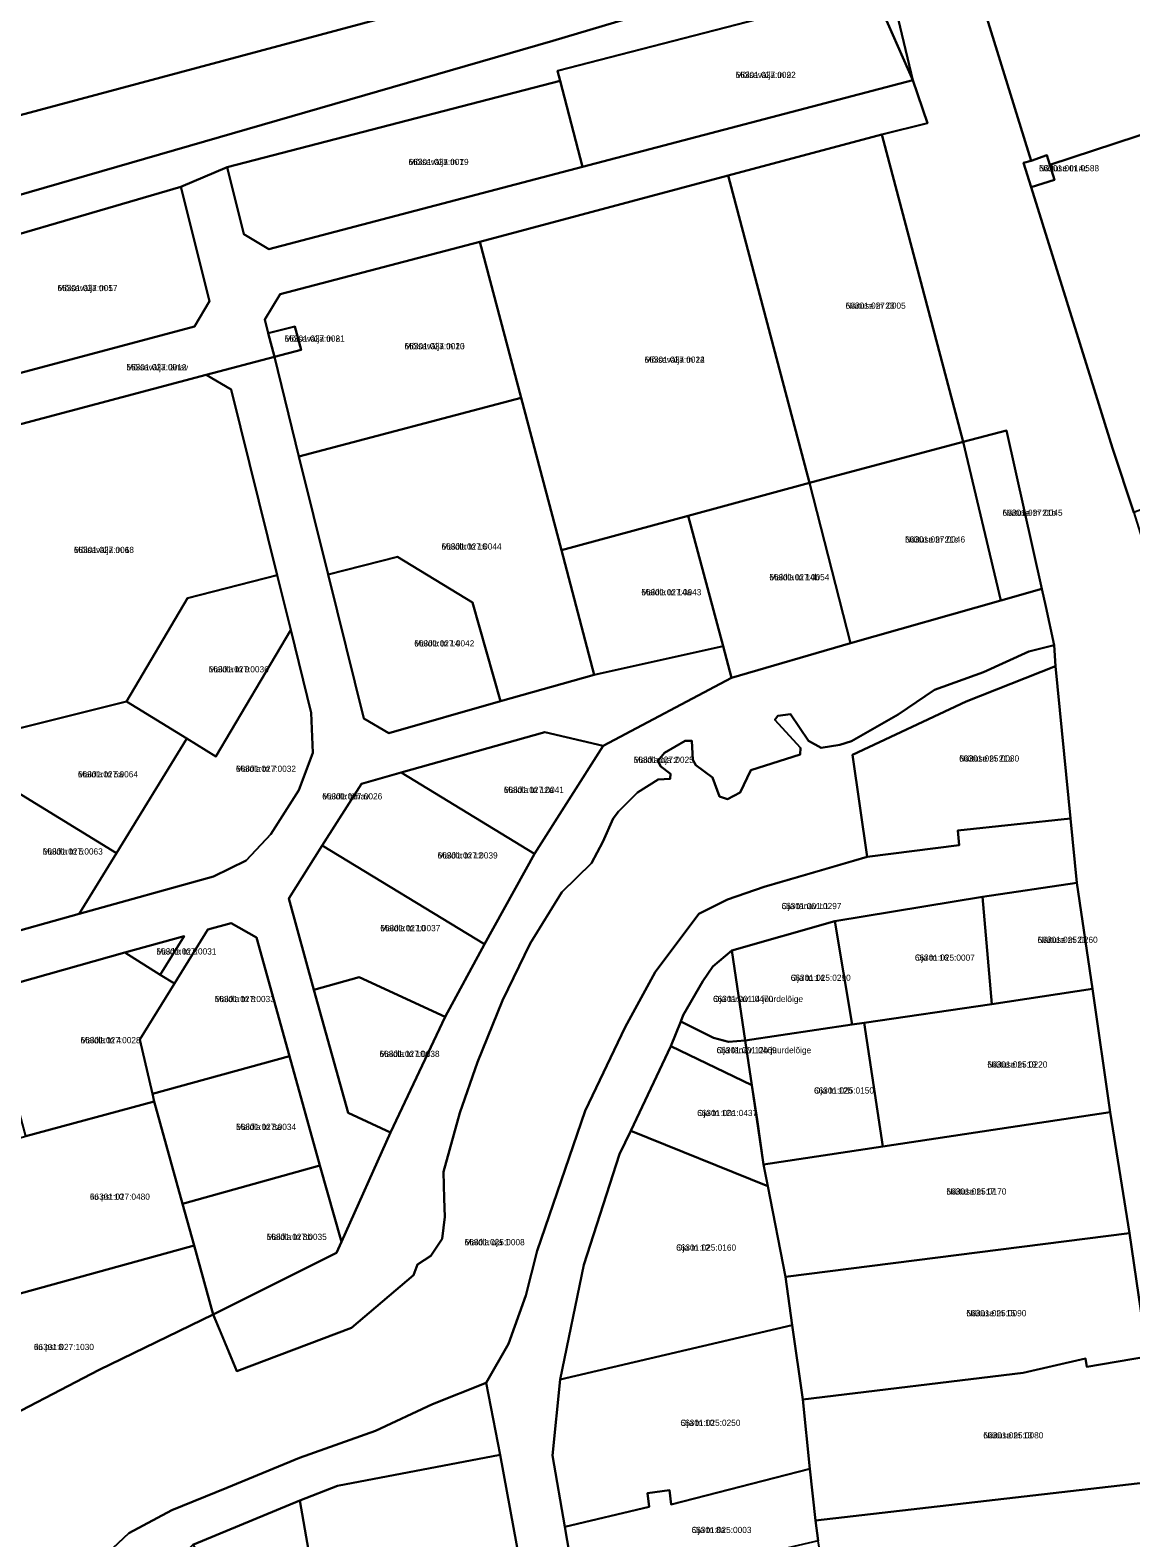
# Model space of a CAD drawing. Extents: x 632278 to 636344, y 6578401 to 6583362.
# Drawn here: x 633256.9 to 633522.9, y 6581626.2 to 6581990.5 of the extents above; entities that cross this region are included whole.
import ezdxf

# ---------------------------------------------------------------- set-up
doc = ezdxf.new("R2010")
doc.units = 0
for name, color, linetype in [('L_AADRESS', 7, 'Continuous'), ('PIIR', 7, 'Continuous'), ('TUNNUS', 7, 'Continuous')]:
    doc.layers.add(name, color=color, linetype=linetype)

msp = doc.modelspace()

# ---------------------------------------------------------------- linework, layer by layer
at = {"layer": 'PIIR'}
for points in [[(633468.65, 6582027.37), (633117.3, 6581933.19), (633092.94, 6581927.34), (633069.22, 6581920.67), (633045.02, 6581914.19), (633045.28, 6581913.19), (633021.21, 6581906.88), (632996.93, 6581900.69), (632973.03, 6581894.3), (632949.09, 6581888.13), (632929.99, 6581882.98), (632922.41, 6581910.15), (633111.38, 6581959.61), (633249.26, 6581995.68), (633462.58, 6582051.42), (633730.08, 6582121.51), (633857.97, 6582155.11), (633862.14, 6582132.61)], [(633580.94, 6582031.55), (633592.88, 6581987.35), (633503.33, 6581957.89), (633502.57, 6581960.28), (633498.8, 6581958.88), (633484.12, 6582006.27)], [(633462.31, 6582011.45), (633470.22, 6581978.42), (633460.53, 6582000.37), (633384.34, 6581980.64), (633384.99, 6581978.2), (633304.52, 6581957.35), (633293.32, 6581952.62), (633225.99, 6581932.99), (633176.07, 6581918.5), (633151, 6581905.14), (633144.21, 6581893.52), (633147.4, 6581879.57), (633151.84, 6581860.05), (633155.06, 6581838.11), (633140.94, 6581889.14), (633140.47, 6581896.81), (633142.13, 6581902.16), (633145.51, 6581907.72), (633153.21, 6581914.67), (633162.26, 6581920.12), (633173.34, 6581925.07), (633203.93, 6581936.06), (633383.2, 6581987.92)], [(633460.53, 6582000.37), (633470.22, 6581978.42), (633390.37, 6581957.42), (633384.99, 6581978.2), (633384.34, 6581980.64)], [(633592.88, 6581987.35), (633613.38, 6581912.42), (633613.99, 6581908.56), (633556.31, 6581886.43), (633523.61, 6581873.92), (633518.47, 6581889.48), (633513.31, 6581906.06), (633498.83, 6581952.55), (633504.43, 6581954.3), (633503.33, 6581957.89)], [(633384.99, 6581978.2), (633390.37, 6581957.42), (633314.61, 6581937.53), (633308.59, 6581941.15), (633304.52, 6581957.35)], [(633425.55, 6581955.33), (633462.71, 6581965.22), (633482.39, 6581890.96), (633445.22, 6581881.09)], [(633498.83, 6581952.55), (633496.97, 6581958.43), (633498.8, 6581958.88), (633502.57, 6581960.28), (633503.33, 6581957.89), (633504.43, 6581954.3)], [(633293.32, 6581952.62), (633300.24, 6581925), (633296.61, 6581918.84), (633234.08, 6581902.2), (633225.99, 6581932.99)], [(633425.55, 6581955.33), (633445.22, 6581881.09), (633415.95, 6581873.12), (633385.29, 6581864.78), (633375.6, 6581901.6), (633365.6, 6581939.32)], [(633365.6, 6581939.32), (633375.6, 6581901.6), (633321.87, 6581887.42), (633315.94, 6581911.51), (633322.39, 6581913.19), (633320.91, 6581918.86), (633314.47, 6581917.28), (633313.68, 6581920.54), (633317.31, 6581926.65)], [(633320.91, 6581918.86), (633322.39, 6581913.19), (633315.94, 6581911.51), (633314.47, 6581917.28)], [(633299.46, 6581907.2), (633305.51, 6581903.66), (633316.61, 6581858.79), (633294.92, 6581853.21), (633280.25, 6581828.25), (633251.58, 6581821.06), (633244.66, 6581846.44), (633225.92, 6581841.42), (633215.22, 6581880.7), (633226.99, 6581887.92)], [(633375.6, 6581901.6), (633385.29, 6581864.78), (633393.19, 6581834.69), (633370.57, 6581828.32), (633363.78, 6581852.14), (633345.66, 6581863.23), (633328.94, 6581858.91), (633321.87, 6581887.42)], [(633492.85, 6581893.71), (633501.36, 6581855.45), (633491.47, 6581852.68), (633482.39, 6581890.96)], [(633482.39, 6581890.96), (633491.47, 6581852.68), (633455.13, 6581842.33), (633445.22, 6581881.09)], [(633445.22, 6581881.09), (633455.13, 6581842.33), (633426.41, 6581833.95), (633424.36, 6581841.62), (633415.95, 6581873.12)], [(633415.95, 6581873.12), (633424.36, 6581841.62), (633393.19, 6581834.69), (633385.29, 6581864.78)], [(633345.66, 6581863.23), (633363.78, 6581852.14), (633370.57, 6581828.32), (633343.56, 6581820.62), (633337.56, 6581824.11), (633328.94, 6581858.91)], [(633316.61, 6581858.79), (633319.93, 6581845.53), (633301.84, 6581814.96), (633294.78, 6581819.28), (633280.25, 6581828.25), (633294.92, 6581853.21)], [(633501.36, 6581855.45), (633502.31, 6581851.17), (633504.37, 6581841.88), (633498.21, 6581840.3), (633487.25, 6581835.35), (633475.45, 6581831.05), (633466.69, 6581825.13), (633455.38, 6581818.69), (633452.59, 6581817.76), (633448.05, 6581817.02), (633445.01, 6581818.76), (633440.68, 6581825.17), (633437.59, 6581824.77), (633436.83, 6581823.79), (633443.06, 6581817.06), (633443, 6581815.44), (633431.04, 6581811.67), (633428.45, 6581806.29), (633425.43, 6581804.67), (633423.51, 6581805.27), (633421.82, 6581809.9), (633417.79, 6581812.83), (633417.05, 6581814.15), (633416.84, 6581818.71), (633415.23, 6581818.78), (633410.23, 6581815.86), (633408.57, 6581813.9), (633409.31, 6581812.58), (633411.67, 6581810.8), (633411.6, 6581809.58), (633408.64, 6581809.44), (633403.66, 6581806.26), (633399.1, 6581801.65), (633397.81, 6581800.02), (633395.34, 6581794.38), (633392.58, 6581789.2), (633385.38, 6581782.22), (633377.76, 6581769.77), (633371.05, 6581756.04), (633365.01, 6581741.12), (633360.77, 6581728.89), (633356.83, 6581714.61), (633356.94, 6581708.2), (633357.17, 6581703.71), (633356.52, 6581698.4), (633353.77, 6581694.28), (633350.54, 6581692.26), (633349.54, 6581689.68), (633334.57, 6581676.88), (633306.84, 6581666.46), (633303, 6581675.83), (633301.19, 6581680.12), (633330.95, 6581695.04), (633332.17, 6581697.67), (633344.04, 6581724.09), (633357.22, 6581752.06), (633366.71, 6581769.58), (633378.77, 6581791.46), (633395.35, 6581817.58), (633426.41, 6581833.95), (633455.13, 6581842.33), (633491.47, 6581852.68)], [(633319.93, 6581845.53), (633324.83, 6581825.48), (633325.22, 6581815.86), (633321.84, 6581806.82), (633315.06, 6581796.22), (633309.13, 6581789.86), (633301.24, 6581785.98), (633268.76, 6581776.98), (633277.77, 6581791.59), (633294.78, 6581819.28), (633301.84, 6581814.96)], [(633455.63, 6581815.4), (633483.06, 6581828.25), (633504.64, 6581836.77), (633508.31, 6581800.02), (633481.05, 6581797.07), (633481.41, 6581793.53), (633459.16, 6581790.72)], [(633251.58, 6581821.06), (633280.25, 6581828.25), (633294.78, 6581819.28), (633277.77, 6581791.59), (633245.6, 6581811.37)], [(633381.26, 6581820.86), (633395.35, 6581817.58), (633378.77, 6581791.46), (633346.62, 6581811.07)], [(633239.57, 6581801.51), (633245.6, 6581811.37), (633277.77, 6581791.59), (633268.76, 6581776.98), (633248, 6581771.16)], [(633346.62, 6581811.07), (633378.77, 6581791.46), (633366.71, 6581769.58), (633327.51, 6581793.45), (633336.99, 6581808.35)], [(633327.51, 6581793.45), (633366.71, 6581769.58), (633357.22, 6581752.06), (633336.45, 6581761.65), (633325.5, 6581758.6), (633319.4, 6581780.68)], [(633487.07, 6581781.04), (633509.79, 6581784.45), (633513.64, 6581758.84), (633489.29, 6581755.15)], [(633487.06, 6581781.03), (633489.29, 6581755.14), (633458.46, 6581750.62), (633455.57, 6581750.22), (633451.36, 6581775.19)], [(633311.64, 6581771.23), (633319.64, 6581742.57), (633286.47, 6581733.48), (633283.46, 6581746.61), (633291.81, 6581760.11), (633299.88, 6581773.15), (633305.49, 6581774.73)], [(633426.51, 6581768.05), (633451.36, 6581775.19), (633455.57, 6581750.22), (633429.72, 6581746.33)], [(633294.17, 6581771.56), (633288.39, 6581762.23), (633279.79, 6581767.57)], [(633291.81, 6581760.11), (633283.46, 6581746.61), (633286.47, 6581733.48), (633286.91, 6581731.59), (633255.93, 6581723.22), (633246.43, 6581758.18), (633279.79, 6581767.57), (633288.39, 6581762.23)], [(633425.66, 6581746.06), (633422.02, 6581746.96), (633414.15, 6581750.94), (633414.75, 6581752.45), (633419.44, 6581760.66), (633421.86, 6581764.21), (633426.51, 6581768.05), (633429.72, 6581746.33)], [(633336.45, 6581761.65), (633357.22, 6581752.06), (633344.04, 6581724.09), (633333.78, 6581728.88), (633325.5, 6581758.6)], [(633458.46, 6581750.62), (633489.29, 6581755.15), (633513.64, 6581758.84), (633517.88, 6581729.04), (633462.92, 6581720.76)], [(633411.77, 6581745.01), (633414.15, 6581750.94), (633422.02, 6581746.96), (633425.66, 6581746.06), (633429.72, 6581746.33), (633431.31, 6581735.58)], [(633429.72, 6581746.33), (633455.57, 6581750.22), (633458.46, 6581750.62), (633462.92, 6581720.76), (633434.16, 6581716.36), (633431.31, 6581735.58)], [(633411.77, 6581745.01), (633431.31, 6581735.58), (633432.56, 6581727.24), (633434.16, 6581716.36), (633435.16, 6581711.15), (633402.06, 6581724.54)], [(633319.64, 6581742.57), (633326.94, 6581716.18), (633293.77, 6581706.88), (633286.91, 6581731.59), (633286.47, 6581733.48)], [(633244.94, 6581706.54), (633252.07, 6581708.73), (633248.95, 6581720.27), (633248.73, 6581721.25), (633255.93, 6581723.22), (633286.91, 6581731.59), (633293.77, 6581706.88), (633296.54, 6581696.84), (633250.78, 6581684.13)], [(633435.16, 6581711.15), (633434.16, 6581716.36), (633462.92, 6581720.76), (633517.88, 6581729.04), (633522.55, 6581699.81), (633439.42, 6581689.21)], [(633390.69, 6581692.12), (633399.32, 6581718.86), (633402.06, 6581724.54), (633435.16, 6581711.15), (633439.42, 6581689.21), (633441.05, 6581677.6), (633384.98, 6581664.44)], [(633326.94, 6581716.18), (633332.17, 6581697.67), (633330.95, 6581695.04), (633301.19, 6581680.12), (633296.54, 6581696.84), (633293.77, 6581706.88)], [(633441.05, 6581677.6), (633439.42, 6581689.21), (633522.55, 6581699.81), (633526.94, 6581670.03), (633512.23, 6581667.49), (633511.9, 6581669.49), (633496.87, 6581666.04), (633443.6, 6581659.61)], [(633230.25, 6581646.23), (633229.72, 6581649.31), (633235.54, 6581659.25), (633232.1, 6581672.26), (633230.76, 6581678.53), (633241.04, 6581681.44), (633250.78, 6581684.13), (633296.54, 6581696.84), (633301.19, 6581680.12), (633273.6, 6581666.8), (633245.43, 6581652.13)], [(633411.44, 6581637.68), (633406.08, 6581637), (633406.53, 6581633.67), (633386.1, 6581628.85), (633383.12, 6581646.09), (633384.98, 6581664.44), (633441.05, 6581677.6), (633443.6, 6581659.61), (633445.34, 6581642.81), (633411.82, 6581634.25)], [(633445.34, 6581642.81), (633443.6, 6581659.61), (633496.87, 6581666.04), (633511.9, 6581669.49), (633512.23, 6581667.49), (633526.94, 6581670.03), (633531.38, 6581640.09), (633446.66, 6581630.36)], [(633236.04, 6581567.1), (633245.27, 6581584.02), (633257.39, 6581602.5), (633270.57, 6581617.68), (633280.81, 6581627.28), (633291.21, 6581632.88), (633304.49, 6581638.25), (633322.01, 6581645.47), (633340.35, 6581652.06), (633354.15, 6581658.45), (633367.14, 6581663.61), (633370.5, 6581646.27), (633331.22, 6581638.78), (633322.09, 6581635.2), (633296.22, 6581624.47), (633281.68, 6581610.06), (633267.35, 6581595.76), (633246.75, 6581561.72)], [(633328.38, 6581599.16), (633322.09, 6581635.2), (633331.22, 6581638.78), (633370.5, 6581646.27), (633377.65, 6581607.17)], [(633386.1, 6581628.85), (633406.53, 6581633.67), (633406.08, 6581637), (633411.44, 6581637.68), (633411.82, 6581634.25), (633445.34, 6581642.81), (633446.66, 6581630.36), (633447.34, 6581625.47), (633388.99, 6581611.85)], [(633450.03, 6581608.95), (633447.34, 6581625.47), (633446.66, 6581630.36), (633531.38, 6581640.09), (633535.56, 6581610.73), (633451.66, 6581597.92)], [(633318.16, 6581595.97), (633318, 6581596.08), (633296.22, 6581624.47), (633322.09, 6581635.2), (633328.38, 6581599.16), (633328.54, 6581598.52)]]:
    msp.add_lwpolyline(points, close=True, dxfattribs=at)
for points in [[(633734.4, 6582070.6), (633580.94, 6582031.55), (633484.12, 6582006.27), (633462.31, 6582011.45), (633383.2, 6581987.92), (633203.93, 6581936.06), (633173.34, 6581925.07), (633162.26, 6581920.12), (633153.21, 6581914.67), (633145.51, 6581907.72), (633142.13, 6581902.16), (633123.55, 6581908.66), (633117.3, 6581933.19), (633468.65, 6582027.37), (633862.14, 6582132.61)], [(633535.56, 6581610.73), (633531.38, 6581640.09), (633526.94, 6581670.03), (633522.55, 6581699.81), (633517.88, 6581729.04), (633513.64, 6581758.84), (633509.79, 6581784.45), (633508.31, 6581800.02), (633504.64, 6581836.77), (633504.37, 6581841.88), (633502.31, 6581851.17), (633501.36, 6581855.45), (633492.85, 6581893.71), (633482.39, 6581890.96), (633462.71, 6581965.22), (633473.75, 6581968.03), (633470.22, 6581978.42), (633462.31, 6582011.45)], [(633484.12, 6582006.27), (633498.8, 6581958.88), (633496.97, 6581958.43), (633498.83, 6581952.55), (633513.31, 6581906.06), (633518.47, 6581889.48), (633523.61, 6581873.92), (633530.92, 6581850.44), (633532.27, 6581846.35), (633541, 6581827.9), (633529.3, 6581787.15), (633527.44, 6581783.44), (633526.6, 6581778.55), (633526.67, 6581768.89), (633540.12, 6581679.97), (633546.05, 6581640.76), (633561.16, 6581540.69)], [(633234.08, 6581902.2), (633296.61, 6581918.84), (633300.24, 6581925), (633293.32, 6581952.62), (633304.52, 6581957.35), (633308.59, 6581941.15), (633314.61, 6581937.53), (633390.37, 6581957.42), (633470.22, 6581978.42), (633473.75, 6581968.03), (633462.71, 6581965.22), (633425.55, 6581955.33), (633365.6, 6581939.32), (633317.31, 6581926.65), (633313.68, 6581920.54), (633314.47, 6581917.28), (633315.94, 6581911.51), (633299.46, 6581907.2), (633226.99, 6581887.92)], [(633248, 6581771.16), (633268.76, 6581776.98), (633301.24, 6581785.98), (633309.13, 6581789.86), (633315.06, 6581796.22), (633321.84, 6581806.82), (633325.22, 6581815.86), (633324.83, 6581825.48), (633319.93, 6581845.53), (633316.61, 6581858.79), (633305.51, 6581903.66), (633299.46, 6581907.2), (633315.94, 6581911.51), (633321.87, 6581887.42), (633328.94, 6581858.91), (633337.56, 6581824.11), (633343.56, 6581820.62), (633370.57, 6581828.32), (633393.19, 6581834.69), (633424.36, 6581841.62), (633426.41, 6581833.95), (633395.35, 6581817.58), (633381.26, 6581820.86), (633346.62, 6581811.07), (633336.99, 6581808.35), (633327.51, 6581793.45), (633319.4, 6581780.68), (633325.5, 6581758.6), (633333.78, 6581728.88), (633344.04, 6581724.09), (633332.17, 6581697.67), (633326.94, 6581716.18), (633319.64, 6581742.57), (633311.64, 6581771.23), (633305.49, 6581774.73), (633299.88, 6581773.15), (633291.81, 6581760.11), (633288.39, 6581762.23), (633294.17, 6581771.56), (633279.79, 6581767.57), (633246.43, 6581758.18)], [(633245.43, 6581652.13), (633273.6, 6581666.8), (633301.19, 6581680.12), (633306.84, 6581666.46), (633334.57, 6581676.88), (633349.54, 6581689.68), (633350.54, 6581692.26), (633353.77, 6581694.28), (633356.52, 6581698.4), (633357.17, 6581703.71), (633356.94, 6581708.2), (633356.83, 6581714.61), (633360.77, 6581728.89), (633365.01, 6581741.12), (633371.05, 6581756.04), (633377.76, 6581769.77), (633385.38, 6581782.22), (633392.58, 6581789.2), (633395.34, 6581794.38), (633397.81, 6581800.02), (633399.1, 6581801.65), (633403.66, 6581806.26), (633408.64, 6581809.44), (633411.6, 6581809.58), (633411.67, 6581810.8), (633409.31, 6581812.58), (633408.57, 6581813.9), (633410.23, 6581815.86), (633415.23, 6581818.78), (633416.84, 6581818.71), (633417.05, 6581814.15), (633417.79, 6581812.83), (633421.82, 6581809.9), (633423.51, 6581805.27), (633425.43, 6581804.67), (633428.45, 6581806.29), (633431.04, 6581811.67), (633443, 6581815.44), (633443.06, 6581817.06), (633436.83, 6581823.79), (633437.59, 6581824.77), (633440.68, 6581825.17), (633445.01, 6581818.76), (633448.05, 6581817.02), (633452.59, 6581817.76), (633455.38, 6581818.69), (633466.69, 6581825.13), (633475.45, 6581831.05), (633487.25, 6581835.35), (633498.21, 6581840.3), (633504.37, 6581841.88), (633504.64, 6581836.77), (633483.06, 6581828.25), (633455.63, 6581815.4), (633459.16, 6581790.72), (633447.92, 6581787.4), (633434.32, 6581783.48), (633425.45, 6581780.39), (633418.5, 6581776.96), (633407.98, 6581762.82), (633400.71, 6581749.54), (633391.04, 6581729.33), (633379.41, 6581695.56), (633376.71, 6581684.77), (633372.55, 6581673.09), (633367.14, 6581663.61), (633354.15, 6581658.45), (633340.35, 6581652.06), (633322.01, 6581645.47), (633304.49, 6581638.25), (633291.21, 6581632.88), (633280.81, 6581627.28), (633270.57, 6581617.68)], [(633377.65, 6581607.17), (633370.5, 6581646.27), (633367.14, 6581663.61), (633372.55, 6581673.09), (633376.71, 6581684.77), (633379.41, 6581695.56), (633391.04, 6581729.33), (633400.71, 6581749.54), (633407.98, 6581762.82), (633418.5, 6581776.96), (633425.45, 6581780.39), (633434.32, 6581783.48), (633459.16, 6581790.72), (633481.41, 6581793.53), (633481.05, 6581797.07), (633508.31, 6581800.02), (633509.79, 6581784.45), (633487.06, 6581781.03), (633451.36, 6581775.19), (633426.51, 6581768.05), (633421.86, 6581764.21), (633419.44, 6581760.66), (633414.75, 6581752.45), (633414.15, 6581750.94), (633411.77, 6581745.01), (633402.06, 6581724.54), (633399.32, 6581718.86), (633390.68, 6581692.12), (633384.98, 6581664.44), (633383.12, 6581646.09), (633386.1, 6581628.85), (633388.99, 6581611.85)]]:
    msp.add_lwpolyline(points, dxfattribs=at)

# ---------------------------------------------------------------- texts
at = {"layer": 'L_AADRESS'}
for s, p in [('Mõisavälja tn 9', (633427.41, 6581978.9)), ('Mõisavälja tn 7', (633348.38, 6581957.87)), ('Näituse tn 4c', (633500.7, 6581956.36)), ('Mõisavälja tn 5', (633263.55, 6581927.41)), ('Näituse tn 23', (633453.97, 6581923.15)), ('Mõisavälja tn 8', (633318.44, 6581915.19)), ('Mõisavälja tn 10', (633347.41, 6581913.37)), ('Mõisavälja tänav', (633280.2, 6581908.27)), ('Mõisavälja tn 12', (633405.41, 6581910.1)), ('Näituse tn 21b', (633491.88, 6581873.12)), ('Näituse tn 21c', (633468.34, 6581866.66)), ('Mõisavälja tn 6', (633267.51, 6581864.13)), ('Maidla tn 16', (633356.34, 6581864.96)), ('Maidla tn 14b', (633435.54, 6581857.53)), ('Maidla tn 14a', (633404.61, 6581853.91)), ('Maidla tn 14', (633349.75, 6581841.55)), ('Maidla tn 9', (633300.09, 6581835.29)), ('Maidla oja 2', (633402.78, 6581813.43)), ('Näituse tn 21a', (633481.4, 6581813.74)), ('Maidla tn 5a', (633268.49, 6581809.92)), ('Maidla tn 7', (633306.67, 6581811.26)), ('Maidla tn 12a', (633371.39, 6581806.16)), ('Maidla tänav', (633327.51, 6581804.59)), ('Maidla tn 5', (633259.99, 6581791.27)), ('Maidla tn 12', (633355.39, 6581790.32)), ('Oja tänav L1', (633438.46, 6581778.09)), ('Maidla tn 10', (633341.54, 6581772.75)), ('Näituse tn 21', (633500.36, 6581769.93)), ('Maidla tn 6', (633287.45, 6581767.12)), ('Oja tn 16', (633470.68, 6581765.62)), ('Oja tn 14', (633440.69, 6581760.76)), ('Maidla tn 8', (633301.55, 6581755.62)), ('Oja tänav 14 juurdelõige', (633421.93, 6581755.64)), ('Maidla tn 4', (633269.12, 6581745.68)), ('Oja tänav 12b juurdelõige', (633422.79, 6581743.26)), ('Maidla tn 10a', (633341.36, 6581742.36)), ('Näituse tn 19', (633488.21, 6581739.8)), ('Oja tn 12b', (633446.32, 6581733.52)), ('Maidla tn 8a', (633306.7, 6581724.73)), ('Oja tn 12a', (633418.09, 6581728.08)), ('Ilu pst 10', (633271.37, 6581707.86)), ('Näituse tn 17', (633478.31, 6581709.12)), ('Maidla tn 8b', (633314.11, 6581698.15)), ('Maidla oja 1', (633361.92, 6581696.87)), ('Oja tn 12', (633413.01, 6581695.56)), ('Näituse tn 15', (633483.13, 6581679.71)), ('Ilu pst 8', (633257.85, 6581671.54)), ('Oja tn 10', (633414.05, 6581653.23)), ('Näituse tn 13', (633487.23, 6581650.2)), ('Oja tn 8a', (633416.72, 6581627.33))]:
    msp.add_text(s, height=1.5, dxfattribs=at).set_placement(p)
at = {"layer": 'TUNNUS'}
for s, p in [('66301:027:0022', (633427.41, 6581978.9)), ('66301:027:0019', (633348.38, 6581957.87)), ('66301:001:0588', (633500.7, 6581956.36)), ('66301:027:0017', (633263.55, 6581927.41)), ('66301:027:0005', (633453.97, 6581923.15)), ('66301:027:0021', (633318.44, 6581915.19)), ('66301:027:0023', (633347.41, 6581913.37)), ('66301:027:0012', (633280.2, 6581908.27)), ('66301:027:0024', (633405.41, 6581910.1)), ('66301:027:0045', (633491.88, 6581873.12)), ('66301:027:0046', (633468.34, 6581866.66)), ('66301:027:0018', (633267.51, 6581864.13)), ('66301:027:0044', (633356.34, 6581864.96)), ('66301:027:0054', (633435.54, 6581857.53)), ('66301:027:0043', (633404.61, 6581853.91)), ('66301:027:0042', (633349.75, 6581841.55)), ('66301:027:0036', (633300.09, 6581835.29)), ('66301:027:0025', (633402.78, 6581813.43)), ('66301:025:0030', (633481.4, 6581813.74)), ('66301:027:0064', (633268.49, 6581809.92)), ('66301:027:0032', (633306.67, 6581811.26)), ('66301:027:0041', (633371.39, 6581806.16)), ('66301:027:0026', (633327.51, 6581804.59)), ('66301:027:0063', (633259.99, 6581791.27)), ('66301:027:0039', (633355.39, 6581790.32)), ('66301:001:0297', (633438.46, 6581778.09)), ('66301:027:0037', (633341.54, 6581772.75)), ('66301:025:0260', (633500.36, 6581769.93)), ('66301:027:0031', (633287.45, 6581767.12)), ('66301:025:0007', (633470.68, 6581765.62)), ('66301:025:0290', (633440.69, 6581760.76)), ('66301:027:0033', (633301.55, 6581755.62)), ('66301:001:0470', (633421.93, 6581755.64)), ('66301:027:0028', (633269.12, 6581745.68)), ('66301:001:0469', (633422.79, 6581743.26)), ('66301:027:0038', (633341.36, 6581742.36)), ('66301:025:0220', (633488.21, 6581739.8)), ('66301:025:0150', (633446.32, 6581733.52)), ('66301:027:0034', (633306.7, 6581724.73)), ('66301:001:0437', (633418.09, 6581728.08)), ('66301:027:0480', (633271.37, 6581707.86)), ('66301:025:0170', (633478.31, 6581709.12)), ('66301:027:0035', (633314.11, 6581698.15)), ('66301:025:0008', (633361.92, 6581696.87)), ('66301:025:0160', (633413.01, 6581695.56)), ('66301:025:0090', (633483.13, 6581679.71)), ('66301:027:1030', (633257.85, 6581671.54)), ('66301:025:0250', (633414.05, 6581653.23)), ('66301:025:0080', (633487.23, 6581650.2)), ('66301:025:0003', (633416.72, 6581627.33))]:
    msp.add_text(s, height=1.5, dxfattribs=at).set_placement(p)

doc.saveas('drawing.dxf')
